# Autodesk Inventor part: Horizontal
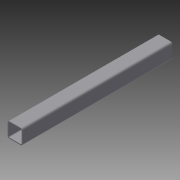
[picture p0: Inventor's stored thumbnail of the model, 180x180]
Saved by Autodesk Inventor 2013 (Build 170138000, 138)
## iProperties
Created: 2008-04
Part Number: Horizontal
Document SubType Name: Modeling
Designer: Jayson Martinez
Density: 1 g/cm^3
Material: Generic
Author: Jayson Martinez
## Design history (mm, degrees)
sketch "Sketch1"
  geometry: L1 (6.35, 0)-(44.45, 0); L2 (50.8, 6.35)-(50.8, 44.45); L3 (44.45, 50.8)-(6.35, 50.8); L4 (0, 44.45)-(0, 6.35); L5 (3.175, 6.35)-(3.175, 44.45); L6 (6.35, 47.625)-(44.45, 47.625); L7 (47.625, 44.45)-(47.625, 6.35); L8 (44.45, 3.175)-(6.35, 3.175); A1 r 6.35 centre (44.45, 44.45) between (50.8, 44.45) and (44.45, 50.8); A2 r 6.35 centre (6.35, 44.45) between (6.35, 50.8) and (0, 44.45); A3 r 6.35 centre (6.35, 6.35) between (0, 6.35) and (6.35, 0); A4 r 6.35 centre (44.45, 6.35) between (44.45, 0) and (50.8, 6.35); A5 r 3.175 centre (6.35, 44.45) between (6.35, 47.625) and (3.175, 44.45); A6 r 3.175 centre (44.45, 44.45) between (47.625, 44.45) and (44.45, 47.625); A7 r 3.175 centre (44.45, 6.35) between (44.45, 3.175) and (47.625, 6.35); A8 r 3.175 centre (6.35, 6.35) between (3.175, 6.35) and (6.35, 3.175); 3 further points
  constraints: 16 end point, 16 point on circle, 8 centre point, 8 tangent, 6 point on line, 4 parallel, 3 equal radius, 2 perpendicular, 1 horizontal, 7 other
  dimensions: "d0" = 50.8 distance of point (0, 0) point (50.8, 0) (= MemberWidth); "d1" = 50.8 distance of point (0, 50.8) point (0, 0) (= MemberWidth); "d2" = 6.35 radius of A1 (= 2 x MemberThickness); "d3" = 3.175 distance between parallel lines of L2 L7 (= MemberThickness)
extrude "Extrusion1" new body sketch "Sketch1" distance "d4" = 508 (= HorizontalLength); taper "d5" = 0 deg
body "Solid1"
other parameters: "MemberThickness" = 3.175, "MemberWidth" = 50.8, "HorizontalLength" = 508
